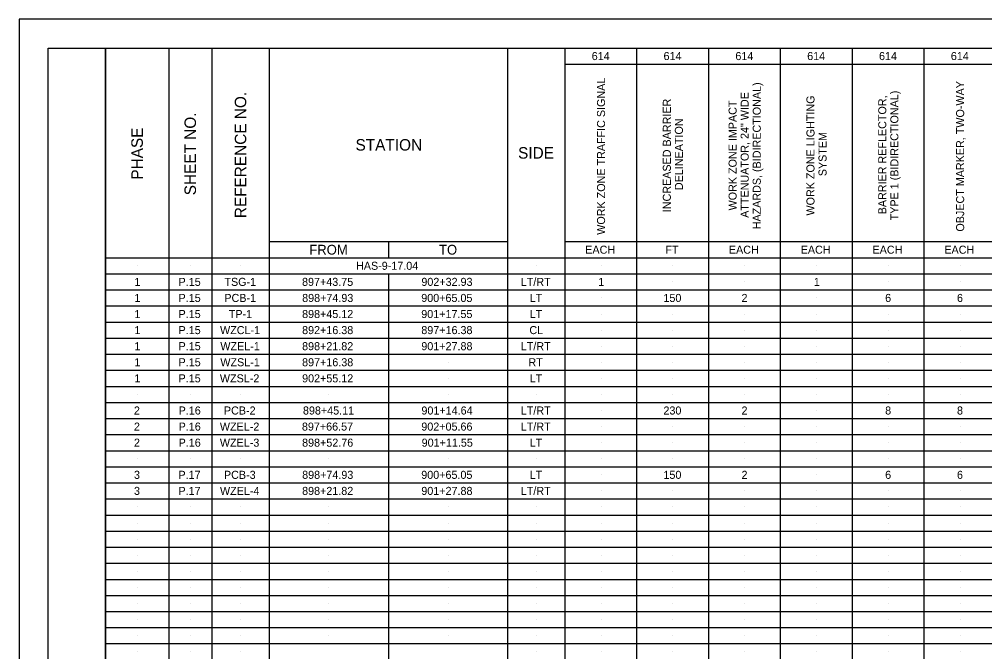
# Model space of a CAD drawing. Extents: x 0 to 66.4, y -22.2 to 22.
# Drawn here: x 0 to 16.8, y 10.99 to 22 of the extents above; entities that cross this region are included whole.
import ezdxf

# ---------------------------------------------------------------- set-up
doc = ezdxf.new("R2010")
doc.units = 0
for name, color, linetype in [('RD_P_Text', 7, 'Continuous'), ('SC_Scratch1', 7, 'Continuous'), ('SC_Scratch2', 7, 'Continuous'), ('SH_Border', 7, 'Continuous'), ('SH_Cut_Line', 7, 'Continuous'), ('SH_Data', 7, 'Continuous')]:
    doc.layers.add(name, color=color, linetype=linetype)

msp = doc.modelspace()

# ---------------------------------------------------------------- linework, layer by layer
at = {"layer": 'SC_Scratch1'}
for p, q in [((10.125, 21.36), (10.125, 21.36)), ((11.375, 21.36), (11.375, 21.36)), ((12.625, 21.36), (12.625, 21.36)), ((13.875, 21.36), (13.875, 21.36)), ((15.125, 21.36), (15.125, 21.36)), ((16.375, 21.36), (16.375, 21.36)), ((10.125, 19.674), (10.125, 19.674)), ((11.375, 19.674), (11.375, 19.674)), ((12.625, 19.674), (12.625, 19.674)), ((13.875, 19.674), (13.875, 19.674)), ((15.125, 19.674), (15.125, 19.674)), ((16.375, 19.674), (16.375, 19.674)), ((10.125, 17.988), (10.125, 17.988)), ((11.375, 17.988), (11.375, 17.988)), ((12.625, 17.988), (12.625, 17.988)), ((13.875, 17.988), (13.875, 17.988)), ((15.125, 17.988), (15.125, 17.988)), ((16.375, 17.988), (16.375, 17.988)), ((2.05, 17.708), (2.05, 17.708)), ((2.975, 17.708), (2.975, 17.708)), ((3.85, 17.708), (3.85, 17.708)), ((9, 17.708), (9, 17.708)), ((10.125, 17.708), (10.125, 17.708)), ((11.375, 17.708), (11.375, 17.708)), ((12.625, 17.708), (12.625, 17.708)), ((13.875, 17.708), (13.875, 17.708)), ((15.125, 17.708), (15.125, 17.708)), ((16.375, 17.708), (16.375, 17.708)), ((2.05, 17.428), (2.05, 17.428)), ((2.975, 17.428), (2.975, 17.428)), ((3.85, 17.428), (3.85, 17.428)), ((9, 17.428), (9, 17.428)), ((10.125, 17.428), (10.125, 17.428)), ((11.375, 17.428), (11.375, 17.428)), ((12.625, 17.428), (12.625, 17.428)), ((13.875, 17.428), (13.875, 17.428)), ((15.125, 17.428), (15.125, 17.428)), ((16.375, 17.428), (16.375, 17.428)), ((2.05, 17.148), (2.05, 17.148)), ((2.975, 17.148), (2.975, 17.148)), ((3.85, 17.148), (3.85, 17.148)), ((9, 17.148), (9, 17.148)), ((10.125, 17.148), (10.125, 17.148)), ((11.375, 17.148), (11.375, 17.148)), ((12.625, 17.148), (12.625, 17.148)), ((13.875, 17.148), (13.875, 17.148)), ((15.125, 17.148), (15.125, 17.148)), ((16.375, 17.148), (16.375, 17.148)), ((2.05, 16.868), (2.05, 16.868)), ((2.975, 16.868), (2.975, 16.868)), ((3.85, 16.868), (3.85, 16.868)), ((9, 16.868), (9, 16.868)), ((10.125, 16.868), (10.125, 16.868)), ((11.375, 16.868), (11.375, 16.868)), ((12.625, 16.868), (12.625, 16.868)), ((13.875, 16.868), (13.875, 16.868)), ((15.125, 16.868), (15.125, 16.868)), ((16.375, 16.868), (16.375, 16.868)), ((2.05, 16.588), (2.05, 16.588)), ((2.975, 16.588), (2.975, 16.588)), ((3.85, 16.588), (3.85, 16.588)), ((9, 16.588), (9, 16.588)), ((10.125, 16.588), (10.125, 16.588)), ((11.375, 16.588), (11.375, 16.588)), ((12.625, 16.588), (12.625, 16.588)), ((13.875, 16.588), (13.875, 16.588)), ((15.125, 16.588), (15.125, 16.588)), ((16.375, 16.588), (16.375, 16.588)), ((2.05, 16.308), (2.05, 16.308)), ((2.975, 16.308), (2.975, 16.308)), ((3.85, 16.308), (3.85, 16.308)), ((9, 16.308), (9, 16.308)), ((10.125, 16.308), (10.125, 16.308)), ((11.375, 16.308), (11.375, 16.308)), ((12.625, 16.308), (12.625, 16.308)), ((13.875, 16.308), (13.875, 16.308)), ((15.125, 16.308), (15.125, 16.308)), ((16.375, 16.308), (16.375, 16.308)), ((2.05, 16.028), (2.05, 16.028)), ((2.975, 16.028), (2.975, 16.028)), ((3.85, 16.028), (3.85, 16.028)), ((9, 16.028), (9, 16.028)), ((10.125, 16.028), (10.125, 16.028)), ((11.375, 16.028), (11.375, 16.028)), ((12.625, 16.028), (12.625, 16.028)), ((13.875, 16.028), (13.875, 16.028)), ((15.125, 16.028), (15.125, 16.028)), ((16.375, 16.028), (16.375, 16.028)), ((2.05, 15.748), (2.05, 15.748)), ((2.975, 15.748), (2.975, 15.748)), ((3.85, 15.748), (3.85, 15.748)), ((9, 15.748), (9, 15.748)), ((10.125, 15.748), (10.125, 15.748)), ((11.375, 15.748), (11.375, 15.748)), ((12.625, 15.748), (12.625, 15.748)), ((13.875, 15.748), (13.875, 15.748)), ((15.125, 15.748), (15.125, 15.748)), ((16.375, 15.748), (16.375, 15.748)), ((2.05, 15.468), (2.05, 15.468)), ((2.975, 15.468), (2.975, 15.468)), ((3.85, 15.468), (3.85, 15.468)), ((9, 15.468), (9, 15.468)), ((10.125, 15.468), (10.125, 15.468)), ((11.375, 15.468), (11.375, 15.468)), ((12.625, 15.468), (12.625, 15.468)), ((13.875, 15.468), (13.875, 15.468)), ((15.125, 15.468), (15.125, 15.468)), ((16.375, 15.468), (16.375, 15.468)), ((2.05, 15.188), (2.05, 15.188)), ((2.975, 15.188), (2.975, 15.188)), ((3.85, 15.188), (3.85, 15.188)), ((9, 15.188), (9, 15.188)), ((10.125, 15.188), (10.125, 15.188)), ((11.375, 15.188), (11.375, 15.188)), ((12.625, 15.188), (12.625, 15.188)), ((13.875, 15.188), (13.875, 15.188)), ((15.125, 15.188), (15.125, 15.188)), ((16.375, 15.188), (16.375, 15.188)), ((2.05, 14.908), (2.05, 14.908)), ((2.975, 14.908), (2.975, 14.908)), ((3.85, 14.908), (3.85, 14.908)), ((9, 14.908), (9, 14.908)), ((10.125, 14.908), (10.125, 14.908)), ((11.375, 14.908), (11.375, 14.908)), ((12.625, 14.908), (12.625, 14.908)), ((13.875, 14.908), (13.875, 14.908)), ((15.125, 14.908), (15.125, 14.908)), ((16.375, 14.908), (16.375, 14.908)), ((2.05, 14.628), (2.05, 14.628)), ((2.975, 14.628), (2.975, 14.628)), ((3.85, 14.628), (3.85, 14.628)), ((9, 14.628), (9, 14.628)), ((10.125, 14.628), (10.125, 14.628)), ((11.375, 14.628), (11.375, 14.628)), ((12.625, 14.628), (12.625, 14.628)), ((13.875, 14.628), (13.875, 14.628)), ((15.125, 14.628), (15.125, 14.628)), ((16.375, 14.628), (16.375, 14.628)), ((2.05, 14.348), (2.05, 14.348)), ((2.975, 14.348), (2.975, 14.348)), ((3.85, 14.348), (3.85, 14.348)), ((9, 14.348), (9, 14.348)), ((10.125, 14.348), (10.125, 14.348)), ((11.375, 14.348), (11.375, 14.348)), ((12.625, 14.348), (12.625, 14.348)), ((13.875, 14.348), (13.875, 14.348)), ((15.125, 14.348), (15.125, 14.348)), ((16.375, 14.348), (16.375, 14.348)), ((2.05, 14.068), (2.05, 14.068)), ((2.975, 14.068), (2.975, 14.068)), ((3.85, 14.068), (3.85, 14.068)), ((9, 14.068), (9, 14.068)), ((10.125, 14.068), (10.125, 14.068)), ((11.375, 14.068), (11.375, 14.068)), ((12.625, 14.068), (12.625, 14.068)), ((13.875, 14.068), (13.875, 14.068)), ((15.125, 14.068), (15.125, 14.068)), ((16.375, 14.068), (16.375, 14.068)), ((2.05, 13.788), (2.05, 13.788)), ((2.975, 13.788), (2.975, 13.788)), ((3.85, 13.788), (3.85, 13.788)), ((9, 13.788), (9, 13.788)), ((10.125, 13.788), (10.125, 13.788)), ((11.375, 13.788), (11.375, 13.788)), ((12.625, 13.788), (12.625, 13.788)), ((13.875, 13.788), (13.875, 13.788)), ((15.125, 13.788), (15.125, 13.788)), ((16.375, 13.788), (16.375, 13.788)), ((2.05, 13.508), (2.05, 13.508)), ((2.975, 13.508), (2.975, 13.508)), ((3.85, 13.508), (3.85, 13.508)), ((9, 13.508), (9, 13.508)), ((10.125, 13.508), (10.125, 13.508)), ((11.375, 13.508), (11.375, 13.508)), ((12.625, 13.508), (12.625, 13.508)), ((13.875, 13.508), (13.875, 13.508)), ((15.125, 13.508), (15.125, 13.508)), ((16.375, 13.508), (16.375, 13.508)), ((2.05, 13.228), (2.05, 13.228)), ((2.975, 13.228), (2.975, 13.228)), ((3.85, 13.228), (3.85, 13.228)), ((9, 13.228), (9, 13.228)), ((10.125, 13.228), (10.125, 13.228)), ((11.375, 13.228), (11.375, 13.228)), ((12.625, 13.228), (12.625, 13.228)), ((13.875, 13.228), (13.875, 13.228)), ((15.125, 13.228), (15.125, 13.228)), ((16.375, 13.228), (16.375, 13.228)), ((2.05, 12.948), (2.05, 12.948)), ((2.975, 12.948), (2.975, 12.948)), ((3.85, 12.948), (3.85, 12.948)), ((9, 12.948), (9, 12.948)), ((10.125, 12.948), (10.125, 12.948)), ((11.375, 12.948), (11.375, 12.948)), ((12.625, 12.948), (12.625, 12.948)), ((13.875, 12.948), (13.875, 12.948)), ((15.125, 12.948), (15.125, 12.948)), ((16.375, 12.948), (16.375, 12.948)), ((2.05, 12.668), (2.05, 12.668)), ((2.975, 12.668), (2.975, 12.668)), ((3.85, 12.668), (3.85, 12.668)), ((9, 12.668), (9, 12.668)), ((10.125, 12.668), (10.125, 12.668)), ((11.375, 12.668), (11.375, 12.668)), ((12.625, 12.668), (12.625, 12.668)), ((13.875, 12.668), (13.875, 12.668)), ((15.125, 12.668), (15.125, 12.668)), ((16.375, 12.668), (16.375, 12.668)), ((2.05, 12.388), (2.05, 12.388)), ((2.975, 12.388), (2.975, 12.388)), ((3.85, 12.388), (3.85, 12.388)), ((9, 12.388), (9, 12.388)), ((10.125, 12.388), (10.125, 12.388)), ((11.375, 12.388), (11.375, 12.388)), ((12.625, 12.388), (12.625, 12.388)), ((13.875, 12.388), (13.875, 12.388)), ((15.125, 12.388), (15.125, 12.388)), ((16.375, 12.388), (16.375, 12.388)), ((2.05, 12.108), (2.05, 12.108)), ((2.975, 12.108), (2.975, 12.108)), ((3.85, 12.108), (3.85, 12.108)), ((9, 12.108), (9, 12.108)), ((10.125, 12.108), (10.125, 12.108)), ((11.375, 12.108), (11.375, 12.108)), ((12.625, 12.108), (12.625, 12.108)), ((13.875, 12.108), (13.875, 12.108)), ((15.125, 12.108), (15.125, 12.108)), ((16.375, 12.108), (16.375, 12.108)), ((2.05, 11.828), (2.05, 11.828)), ((2.975, 11.828), (2.975, 11.828)), ((3.85, 11.828), (3.85, 11.828)), ((9, 11.828), (9, 11.828)), ((10.125, 11.828), (10.125, 11.828)), ((11.375, 11.828), (11.375, 11.828)), ((12.625, 11.828), (12.625, 11.828)), ((13.875, 11.828), (13.875, 11.828)), ((15.125, 11.828), (15.125, 11.828)), ((16.375, 11.828), (16.375, 11.828)), ((2.05, 11.548), (2.05, 11.548)), ((2.975, 11.548), (2.975, 11.548)), ((3.85, 11.548), (3.85, 11.548)), ((9, 11.548), (9, 11.548)), ((10.125, 11.548), (10.125, 11.548)), ((11.375, 11.548), (11.375, 11.548)), ((12.625, 11.548), (12.625, 11.548)), ((13.875, 11.548), (13.875, 11.548)), ((15.125, 11.548), (15.125, 11.548)), ((16.375, 11.548), (16.375, 11.548)), ((2.05, 11.268), (2.05, 11.268)), ((2.975, 11.268), (2.975, 11.268)), ((3.85, 11.268), (3.85, 11.268)), ((9, 11.268), (9, 11.268)), ((10.125, 11.268), (10.125, 11.268)), ((11.375, 11.268), (11.375, 11.268)), ((12.625, 11.268), (12.625, 11.268)), ((13.875, 11.268), (13.875, 11.268)), ((15.125, 11.268), (15.125, 11.268)), ((16.375, 11.268), (16.375, 11.268)), ((2.05, 10.988), (2.05, 10.988)), ((2.975, 10.988), (2.975, 10.988)), ((3.85, 10.988), (3.85, 10.988)), ((9, 10.988), (9, 10.988)), ((10.125, 10.988), (10.125, 10.988)), ((11.375, 10.988), (11.375, 10.988)), ((12.625, 10.988), (12.625, 10.988)), ((13.875, 10.988), (13.875, 10.988)), ((15.125, 10.988), (15.125, 10.988)), ((16.375, 10.988), (16.375, 10.988))]:
    msp.add_line(p, q, dxfattribs=at)
at = {"layer": 'SC_Scratch2'}
for p, q in [((6.425, 17.708), (6.425, 17.708)), ((5.388, 17.428), (5.388, 17.428)), ((7.462, 17.428), (7.462, 17.428)), ((5.388, 17.148), (5.388, 17.148)), ((7.462, 17.148), (7.462, 17.148)), ((5.388, 16.868), (5.388, 16.868)), ((7.462, 16.868), (7.462, 16.868)), ((5.388, 16.588), (5.388, 16.588)), ((7.462, 16.588), (7.462, 16.588)), ((5.388, 16.308), (5.388, 16.308)), ((7.462, 16.308), (7.462, 16.308)), ((5.388, 16.028), (5.388, 16.028)), ((7.462, 16.028), (7.462, 16.028)), ((5.388, 15.748), (5.388, 15.748)), ((7.462, 15.748), (7.462, 15.748)), ((5.388, 15.468), (5.388, 15.468)), ((7.462, 15.468), (7.462, 15.468)), ((5.388, 15.188), (5.388, 15.188)), ((7.462, 15.188), (7.462, 15.188)), ((5.388, 14.908), (5.388, 14.908)), ((7.462, 14.908), (7.462, 14.908)), ((5.388, 14.628), (5.388, 14.628)), ((7.462, 14.628), (7.462, 14.628)), ((5.388, 14.348), (5.388, 14.348)), ((7.462, 14.348), (7.462, 14.348)), ((5.388, 14.068), (5.388, 14.068)), ((7.462, 14.068), (7.462, 14.068)), ((5.388, 13.788), (5.388, 13.788)), ((7.462, 13.788), (7.462, 13.788)), ((5.388, 13.508), (5.388, 13.508)), ((7.462, 13.508), (7.462, 13.508)), ((5.388, 13.228), (5.388, 13.228)), ((7.462, 13.228), (7.462, 13.228)), ((5.388, 12.948), (5.388, 12.948)), ((7.462, 12.948), (7.462, 12.948)), ((5.388, 12.668), (5.388, 12.668)), ((7.462, 12.668), (7.462, 12.668)), ((5.388, 12.388), (5.388, 12.388)), ((7.462, 12.388), (7.462, 12.388)), ((5.388, 12.108), (5.388, 12.108)), ((7.462, 12.108), (7.462, 12.108)), ((5.388, 11.828), (5.388, 11.828)), ((7.462, 11.828), (7.462, 11.828)), ((5.388, 11.548), (5.388, 11.548)), ((7.462, 11.548), (7.462, 11.548)), ((5.388, 11.268), (5.388, 11.268)), ((7.462, 11.268), (7.462, 11.268))]:
    msp.add_line(p, q, dxfattribs=at)
at = {"layer": 'SH_Border'}
msp.add_line((2.6, 21.5), (2.6, 1.048), dxfattribs=at)
for points in [[(0.5, 21.5), (1.5, 21.5), (1.5, 0.5), (0.5, 0.5)], [(1.5, 21.5), (33.5, 21.5), (33.5, 0.5), (1.5, 0.5)]]:
    msp.add_lwpolyline(points, close=True, dxfattribs=at)
at = {"layer": 'SH_Cut_Line'}
msp.add_lwpolyline([(0, 0), (34, 0), (34, 22), (0, 22)], close=True, dxfattribs=at)
at = {"layer": 'SH_Data'}
for p, q in [((3.35, 21.5), (3.35, 1.048)), ((4.35, 21.5), (4.35, 1.048)), ((8.5, 1.048), (8.5, 21.5)), ((9.5, 0.5), (9.5, 21.5)), ((10.75, 0.5), (10.75, 21.5)), ((12, 0.5), (12, 21.5)), ((13.25, 0.5), (13.25, 21.5)), ((14.5, 0.5), (14.5, 21.5)), ((15.75, 0.5), (15.75, 21.5)), ((9.5, 21.22), (32, 21.22)), ((4.35, 18.128), (8.5, 18.128)), ((6.425, 18.128), (6.425, 17.848)), ((9.5, 18.128), (32, 18.128)), ((1.5, 17.848), (32, 17.848)), ((1.5, 17.568), (32, 17.568)), ((6.425, 17.568), (6.425, 1.048)), ((1.5, 17.288), (32, 17.288)), ((1.5, 17.008), (32, 17.008)), ((1.5, 16.728), (32, 16.728)), ((1.5, 16.448), (32, 16.448)), ((1.5, 16.168), (32, 16.168)), ((1.5, 15.888), (32, 15.888)), ((1.5, 15.608), (32, 15.608)), ((1.5, 15.328), (32, 15.328)), ((1.5, 15.048), (32, 15.048)), ((1.5, 14.768), (32, 14.768)), ((1.5, 14.488), (32, 14.488)), ((1.5, 14.208), (32, 14.208)), ((1.5, 13.928), (32, 13.928)), ((1.5, 13.648), (32, 13.648)), ((1.5, 13.368), (32, 13.368)), ((1.5, 13.088), (32, 13.088)), ((1.5, 12.808), (32, 12.808)), ((1.5, 12.528), (32, 12.528)), ((1.5, 12.248), (32, 12.248)), ((1.5, 11.968), (32, 11.968)), ((1.5, 11.688), (32, 11.688)), ((1.5, 11.408), (32, 11.408)), ((1.5, 11.128), (32, 11.128))]:
    msp.add_line(p, q, dxfattribs=at)

# ---------------------------------------------------------------- texts
at = {"layer": 'RD_P_Text'}
for s, p in [('614', (9.963, 21.29)), ('614', (11.213, 21.29)), ('614', (12.463, 21.29)), ('614', (13.713, 21.29)), ('614', (14.963, 21.29)), ('614', (16.213, 21.29)), ('EACH', (9.85, 17.918)), ('FT', (11.246, 17.918)), ('EACH', (12.35, 17.918)), ('EACH', (13.6, 17.918)), ('EACH', (14.85, 17.918)), ('EACH', (16.1, 17.918)), ('HAS-9-17.04', (5.861, 17.638)), ('1', (2.003, 17.358)), ('P.15', (2.772, 17.358)), ('TSG-1', (3.57, 17.358)), ('897+43.75', (4.921, 17.358)), ('902+32.93', (6.998, 17.358)), ('LT/RT', (8.728, 17.358)), ('1', (10.078, 17.358)), ('1', (13.828, 17.358)), ('1', (2.003, 17.078)), ('P.15', (2.772, 17.078)), ('PCB-1', (3.569, 17.078)), ('898+74.93', (4.923, 17.078)), ('900+65.05', (6.996, 17.078)), ('LT', (8.883, 17.078)), ('150', (11.211, 17.078)), ('2', (12.57, 17.078)), ('6', (15.07, 17.078)), ('6', (16.32, 17.078)), ('1', (2.003, 16.798)), ('P.15', (2.772, 16.798)), ('TP-1', (3.646, 16.798)), ('898+45.12', (4.922, 16.798)), ('901+17.55', (6.996, 16.798)), ('LT', (8.883, 16.798)), ('1', (2.003, 16.518)), ('P.15', (2.772, 16.518)), ('WZCL-1', (3.494, 16.518)), ('892+16.38', (4.922, 16.518)), ('897+16.38', (6.997, 16.518)), ('CL', (8.878, 16.518)), ('1', (2.003, 16.238)), ('P.15', (2.772, 16.238)), ('WZEL-1', (3.499, 16.238)), ('898+21.82', (4.922, 16.238)), ('901+27.88', (6.997, 16.238)), ('LT/RT', (8.728, 16.238)), ('1', (2.003, 15.958)), ('P.15', (2.772, 15.958)), ('WZSL-1', (3.499, 15.958)), ('897+16.38', (4.922, 15.958)), ('RT', (8.862, 15.958)), ('1', (2.003, 15.678)), ('P.15', (2.772, 15.678)), ('WZSL-2', (3.491, 15.678)), ('902+55.12', (4.922, 15.678)), ('LT', (8.883, 15.678)), ('2', (1.995, 15.118)), ('P.16', (2.773, 15.118)), ('PCB-2', (3.561, 15.118)), ('898+45.11', (4.937, 15.118)), ('901+14.64', (6.999, 15.118)), ('LT/RT', (8.728, 15.118)), ('230', (11.211, 15.118)), ('2', (12.57, 15.118)), ('8', (15.07, 15.118)), ('8', (16.32, 15.118)), ('2', (1.995, 14.838)), ('P.16', (2.773, 14.838)), ('WZEL-2', (3.491, 14.838)), ('897+66.57', (4.919, 14.838)), ('902+05.66', (6.997, 14.838)), ('LT/RT', (8.728, 14.838)), ('2', (1.995, 14.558)), ('P.16', (2.773, 14.558)), ('WZEL-3', (3.491, 14.558)), ('898+52.76', (4.922, 14.558)), ('901+11.55', (7.003, 14.558)), ('LT', (8.883, 14.558)), ('3', (1.996, 13.998)), ('P.17', (2.77, 13.998)), ('PCB-3', (3.562, 13.998)), ('898+74.93', (4.923, 13.998)), ('900+65.05', (6.996, 13.998)), ('LT', (8.883, 13.998)), ('150', (11.211, 13.998)), ('2', (12.57, 13.998)), ('6', (15.07, 13.998)), ('6', (16.32, 13.998)), ('3', (1.996, 13.718)), ('P.17', (2.77, 13.718)), ('WZEL-4', (3.493, 13.718)), ('898+21.82', (4.922, 13.718)), ('901+27.88', (6.997, 13.718)), ('LT/RT', (8.728, 13.718))]:
    msp.add_text(s, height=0.14, dxfattribs=at).set_placement(p)
for s, p in [('WORK ZONE TRAFFIC SIGNAL', (10.195, 18.248)), ('HAZARDS, (BIDIRECTIONAL)', (12.905, 18.343)), ('OBJECT MARKER, TWO-WAY', (16.445, 18.303)), ('ATTENUATOR, 24" WIDE ', (12.695, 18.543)), ('TYPE 1 (BIDIRECTIONAL)', (15.3, 18.5)), ('INCREASED BARRIER ', (11.34, 18.641)), ('WORK ZONE IMPACT ', (12.485, 18.672)), ('WORK ZONE LIGHTING ', (13.84, 18.583)), ('BARRIER REFLECTOR,', (15.09, 18.604)), ('DELINEATION', (11.55, 19.026)), ('SYSTEM', (14.05, 19.268))]:
    msp.add_text(s, height=0.14, rotation=90, dxfattribs=at).set_placement(p)
at = {"layer": 'SH_Data'}
for s, p in [('REFERENCE NO.', (3.95, 18.537)), ('SHEET NO.', (3.075, 18.936)), ('PHASE', (2.15, 19.208))]:
    msp.add_text(s, height=0.2, rotation=90, dxfattribs=at).set_placement(p)
for s, height, p in [('STATION', 0.2, (5.852, 19.714)), ('SIDE', 0.2, (8.681, 19.574)), ('FROM', 0.17, (5.047, 17.903)), ('TO', 0.17, (7.305, 17.903))]:
    msp.add_text(s, height=height, dxfattribs=at).set_placement(p)

doc.saveas('drawing.dxf')
